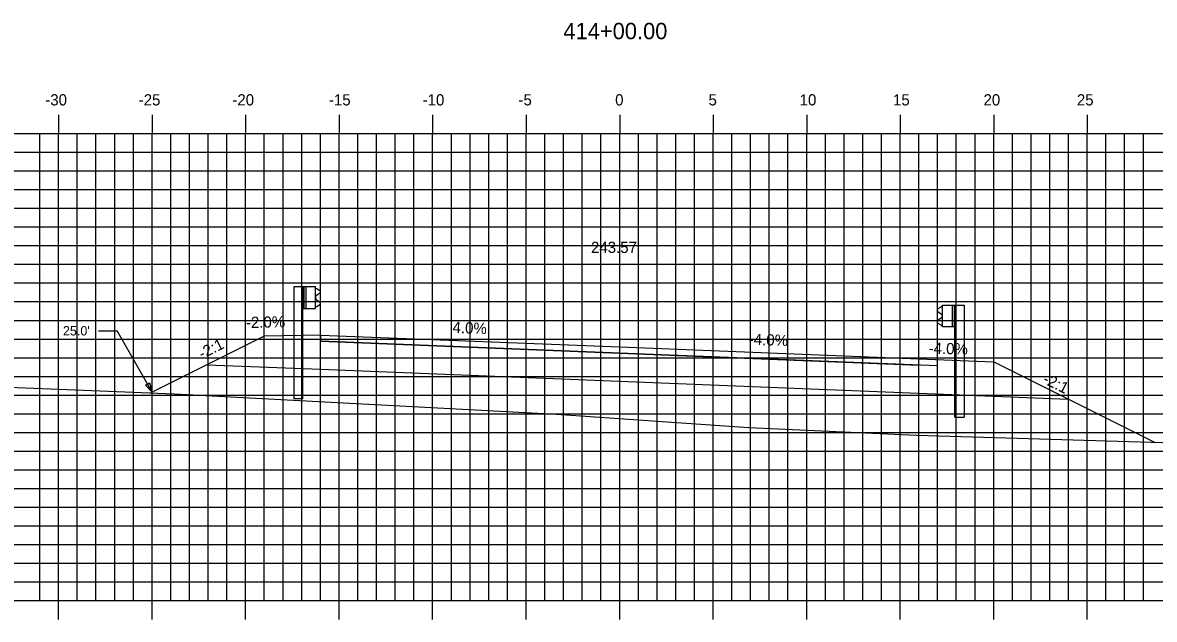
# Model space of a CAD drawing. Extents: x 1160718 to 1173142, y 616002 to 617630.
# Drawn here: x 1168156.4 to 1168216.9, y 616656.9 to 616688.9 of the extents above; entities that cross this region are included whole.
import ezdxf

# ---------------------------------------------------------------- set-up
doc = ezdxf.new("R2010")
doc.units = 0
for name, color, linetype in [('ANNOTATION', 7, 'Continuous'), ('D_Guardrail_Beam_Lt', 7, 'Continuous'), ('D_Guardrail_Beam_Rt', 7, 'Continuous'), ('D_Roadway_Centerline', 7, 'Continuous'), ('D_Roadway_Centerline_Text', 7, 'Continuous'), ('D_Roadway_Edge_Shoulder', 7, 'Continuous'), ('D_Roadway_Edge_TW', 7, 'Continuous'), ('D_Roadway_Pavement', 7, 'Continuous'), ('D_Roadway_SlopeLines', 7, 'Continuous'), ('D_Roadway_SubGrade', 7, 'Continuous'), ('H_V ANNOTATION', 7, 'Continuous'), ('MAJOR', 7, 'Continuous'), ('MINOR', 7, 'Continuous'), ('S_Roadway_Centerline', 7, 'Continuous'), ('SHADING', 7, 'Continuous')]:
    doc.layers.add(name, color=color, linetype=linetype)

msp = doc.modelspace()

# ---------------------------------------------------------------- linework, layer by layer
at = {"layer": 'ANNOTATION'}
for p, q in [((1168160.476, 616672.369), (1168161.476, 616672.369)), ((1168163.342, 616669.083), (1168161.476, 616672.369)), ((1168204.342, 616670.863), (1168208.338, 616670.703))]:
    msp.add_line(p, q, dxfattribs=at)
msp.add_lwpolyline([(1168163.203, 616669.579), (1168163.342, 616669.083), (1168162.986, 616669.456)], close=True, dxfattribs=at)
at = {"layer": 'D_Guardrail_Beam_Lt'}
for p, q in [((1168170.916, 616674.726), (1168170.916, 616668.726)), ((1168171.387, 616674.726), (1168170.916, 616674.726)), ((1168172.074, 616674.726), (1168171.387, 616674.726)), ((1168171.387, 616674.726), (1168171.387, 616673.559)), ((1168171.449, 616674.726), (1168171.449, 616673.559)), ((1168171.553, 616674.726), (1168171.553, 616673.559)), ((1168172.074, 616673.559), (1168172.074, 616674.726)), ((1168172.074, 616674.643), (1168172.148, 616674.628)), ((1168172.164, 616674.621), (1168172.308, 616674.521)), ((1168172.079, 616674.178), (1168172.079, 616674.108)), ((1168172.308, 616674.378), (1168172.112, 616674.242)), ((1168172.112, 616674.043), (1168172.308, 616673.907)), ((1168171.387, 616673.559), (1168172.074, 616673.559)), ((1168171.408, 616668.726), (1168171.408, 616673.559)), ((1168172.148, 616673.657), (1168172.074, 616673.643)), ((1168172.308, 616673.764), (1168172.164, 616673.664)), ((1168171.408, 616668.726), (1168170.916, 616668.726))]:
    msp.add_line(p, q, dxfattribs=at)
for centre, major_axis, start_param, end_param in [((1168172.14, 616674.587), (0.0417, 0), 0.959931, 1.376053), ((1168172.257, 616674.45), (0.0877, 0), 5.323254, 7.243116), ((1168172.158, 616674.178), (-0.0789, 0), 5.323254, 6.283185), ((1168172.158, 616674.108), (-0.0789, 0), 6.283185, 7.243116), ((1168172.257, 616673.836), (0.0877, 0), 5.323254, 7.243116), ((1168172.14, 616673.698), (0.0417, 0), 4.907132, 5.323254)]:
    msp.add_ellipse(centre, major_axis=major_axis, ratio=0.995501, start_param=start_param, end_param=end_param, dxfattribs=at)
at = {"layer": 'D_Guardrail_Beam_Rt'}
for p, q in [((1168205.505, 616673.638), (1168205.361, 616673.538)), ((1168205.361, 616673.394), (1168205.557, 616673.258)), ((1168205.595, 616673.659), (1168205.521, 616673.644)), ((1168205.595, 616673.742), (1168206.282, 616673.742)), ((1168205.595, 616672.575), (1168205.595, 616673.742)), ((1168206.116, 616673.742), (1168206.116, 616672.575)), ((1168206.22, 616673.742), (1168206.22, 616672.575)), ((1168206.282, 616673.742), (1168206.753, 616673.742)), ((1168206.282, 616673.742), (1168206.282, 616672.575)), ((1168206.753, 616673.742), (1168206.753, 616667.742)), ((1168205.557, 616673.059), (1168205.361, 616672.923)), ((1168205.361, 616672.78), (1168205.505, 616672.68)), ((1168205.521, 616672.673), (1168205.595, 616672.659)), ((1168205.59, 616673.194), (1168205.59, 616673.124)), ((1168206.282, 616672.575), (1168205.595, 616672.575)), ((1168206.261, 616667.742), (1168206.261, 616672.575)), ((1168206.261, 616667.742), (1168206.753, 616667.742))]:
    msp.add_line(p, q, dxfattribs=at)
for centre, major_axis, start_param, end_param in [((1168205.412, 616673.466), (-0.0877, 0), 5.323254, 7.243116), ((1168205.529, 616673.604), (-0.0417, 0), 4.907132, 5.323254), ((1168205.511, 616673.194), (0.0789, 0), 0, 0.959931), ((1168205.412, 616672.852), (-0.0877, 0), 5.323254, 7.243116), ((1168205.529, 616672.714), (-0.0417, 0), 0.959931, 1.376053), ((1168205.511, 616673.124), (0.0789, 0), 5.323254, 6.283185)]:
    msp.add_ellipse(centre, major_axis=major_axis, ratio=0.995501, start_param=start_param, end_param=end_param, dxfattribs=at)
at = {"layer": 'D_Roadway_Edge_Shoulder'}
msp.add_lwpolyline([(1168172.342, 616672.143), (1168172.342, 616671.81)], dxfattribs=at)
at = {"layer": 'D_Roadway_Edge_TW'}
for p, q in [((1168172.342, 616671.81), (1168172.342, 616672.143)), ((1168172.342, 616672.143), (1168188.342, 616671.503)), ((1168188.342, 616671.17), (1168172.342, 616671.81)), ((1168188.342, 616671.503), (1168204.342, 616670.863)), ((1168205.342, 616670.49), (1168188.342, 616671.17))]:
    msp.add_line(p, q, dxfattribs=at)
at = {"layer": 'D_Roadway_Pavement'}
msp.add_lwpolyline([(1168172.342, 616671.81), (1168172.342, 616671.81), (1168188.342, 616671.17), (1168204.342, 616670.53), (1168204.342, 616670.53), (1168188.342, 616671.17)], close=True, dxfattribs=at)
for points in [[(1168172.342, 616671.81), (1168172.342, 616671.81)], [(1168172.342, 616671.81), (1168172.342, 616671.81)], [(1168204.342, 616670.53), (1168204.342, 616670.53)], [(1168204.342, 616670.53), (1168204.342, 616670.53)]]:
    msp.add_lwpolyline(points, dxfattribs=at)
at = {"layer": 'D_Roadway_SlopeLines'}
for points in [[(1168169.342, 616672.083), (1168163.283, 616669.054)], [(1168208.342, 616670.703), (1168216.931, 616666.408)]]:
    msp.add_lwpolyline(points, dxfattribs=at)
at = {"layer": 'D_Roadway_SubGrade'}
for p, q in [((1168172.342, 616672.143), (1168169.342, 616672.083)), ((1168172.342, 616670.31), (1168172.342, 616672.143)), ((1168172.342, 616670.31), (1168172.342, 616671.81)), ((1168172.342, 616671.81), (1168188.342, 616671.17)), ((1168188.342, 616671.17), (1168204.342, 616670.53)), ((1168205.342, 616668.99), (1168205.342, 616670.823))]:
    msp.add_line(p, q, dxfattribs=at)
at = {"layer": 'MAJOR'}
for p, q in [((1168158.342, 616683.93), (1168158.342, 616682.928)), ((1168163.342, 616683.93), (1168163.342, 616682.928)), ((1168168.342, 616683.93), (1168168.342, 616682.928)), ((1168173.342, 616683.93), (1168173.342, 616682.928)), ((1168178.342, 616683.93), (1168178.342, 616682.928)), ((1168183.342, 616683.93), (1168183.342, 616682.928)), ((1168188.342, 616683.93), (1168188.342, 616682.928)), ((1168193.342, 616683.93), (1168193.342, 616682.928)), ((1168198.342, 616683.93), (1168198.342, 616682.928)), ((1168203.342, 616683.93), (1168203.342, 616682.928)), ((1168208.342, 616683.93), (1168208.342, 616682.928)), ((1168213.342, 616683.93), (1168213.342, 616682.928)), ((1168118.342, 616682.928), (1168258.342, 616682.928)), ((1168118.342, 616682.928), (1168258.342, 616682.928)), ((1168158.342, 616657.928), (1168158.342, 616682.928)), ((1168163.342, 616657.928), (1168163.342, 616682.928)), ((1168168.342, 616657.928), (1168168.342, 616682.928)), ((1168173.342, 616657.928), (1168173.342, 616682.928)), ((1168178.342, 616657.928), (1168178.342, 616682.928)), ((1168183.342, 616657.928), (1168183.342, 616682.928)), ((1168188.342, 616657.928), (1168188.342, 616682.928)), ((1168193.342, 616657.928), (1168193.342, 616682.928)), ((1168198.342, 616657.928), (1168198.342, 616682.928)), ((1168203.342, 616657.928), (1168203.342, 616682.928)), ((1168208.342, 616657.928), (1168208.342, 616682.928)), ((1168213.342, 616657.928), (1168213.342, 616682.928)), ((1168118.342, 616677.928), (1168258.342, 616677.928)), ((1168118.342, 616672.928), (1168258.342, 616672.928)), ((1168118.342, 616667.928), (1168258.342, 616667.928)), ((1168118.342, 616662.928), (1168258.342, 616662.928)), ((1168118.342, 616657.928), (1168258.342, 616657.928)), ((1168118.342, 616657.928), (1168258.342, 616657.928)), ((1168158.342, 616656.926), (1168158.342, 616657.928)), ((1168163.342, 616656.926), (1168163.342, 616657.928)), ((1168168.342, 616656.926), (1168168.342, 616657.928)), ((1168173.342, 616656.926), (1168173.342, 616657.928)), ((1168178.342, 616656.926), (1168178.342, 616657.928)), ((1168183.342, 616656.926), (1168183.342, 616657.928)), ((1168188.342, 616656.926), (1168188.342, 616657.928)), ((1168193.342, 616656.926), (1168193.342, 616657.928)), ((1168198.342, 616656.926), (1168198.342, 616657.928)), ((1168203.342, 616656.926), (1168203.342, 616657.928)), ((1168208.342, 616656.926), (1168208.342, 616657.928)), ((1168213.342, 616656.926), (1168213.342, 616657.928))]:
    msp.add_line(p, q, dxfattribs=at)
at = {"layer": 'MINOR'}
for p, q in [((1168157.342, 616657.928), (1168157.342, 616682.928)), ((1168159.342, 616657.928), (1168159.342, 616682.928)), ((1168160.342, 616657.928), (1168160.342, 616682.928)), ((1168161.342, 616657.928), (1168161.342, 616682.928)), ((1168162.342, 616657.928), (1168162.342, 616682.928)), ((1168164.342, 616657.928), (1168164.342, 616682.928)), ((1168165.342, 616657.928), (1168165.342, 616682.928)), ((1168166.342, 616657.928), (1168166.342, 616682.928)), ((1168167.342, 616657.928), (1168167.342, 616682.928)), ((1168169.342, 616657.928), (1168169.342, 616682.928)), ((1168170.342, 616657.928), (1168170.342, 616682.928)), ((1168171.342, 616657.928), (1168171.342, 616682.928)), ((1168172.342, 616657.928), (1168172.342, 616682.928)), ((1168174.342, 616657.928), (1168174.342, 616682.928)), ((1168175.342, 616657.928), (1168175.342, 616682.928)), ((1168176.342, 616657.928), (1168176.342, 616682.928)), ((1168177.342, 616657.928), (1168177.342, 616682.928)), ((1168179.342, 616657.928), (1168179.342, 616682.928)), ((1168180.342, 616657.928), (1168180.342, 616682.928)), ((1168181.342, 616657.928), (1168181.342, 616682.928)), ((1168182.342, 616657.928), (1168182.342, 616682.928)), ((1168184.342, 616657.928), (1168184.342, 616682.928)), ((1168185.342, 616657.928), (1168185.342, 616682.928)), ((1168186.342, 616657.928), (1168186.342, 616682.928)), ((1168187.342, 616657.928), (1168187.342, 616682.928)), ((1168189.342, 616657.928), (1168189.342, 616682.928)), ((1168190.342, 616657.928), (1168190.342, 616682.928)), ((1168191.342, 616657.928), (1168191.342, 616682.928)), ((1168192.342, 616657.928), (1168192.342, 616682.928)), ((1168194.342, 616657.928), (1168194.342, 616682.928)), ((1168195.342, 616657.928), (1168195.342, 616682.928)), ((1168196.342, 616657.928), (1168196.342, 616682.928)), ((1168197.342, 616657.928), (1168197.342, 616682.928)), ((1168199.342, 616657.928), (1168199.342, 616682.928)), ((1168200.342, 616657.928), (1168200.342, 616682.928)), ((1168201.342, 616657.928), (1168201.342, 616682.928)), ((1168202.342, 616657.928), (1168202.342, 616682.928)), ((1168204.342, 616657.928), (1168204.342, 616682.928)), ((1168205.342, 616657.928), (1168205.342, 616682.928)), ((1168206.342, 616657.928), (1168206.342, 616682.928)), ((1168207.342, 616657.928), (1168207.342, 616682.928)), ((1168209.342, 616657.928), (1168209.342, 616682.928)), ((1168210.342, 616657.928), (1168210.342, 616682.928)), ((1168211.342, 616657.928), (1168211.342, 616682.928)), ((1168212.342, 616657.928), (1168212.342, 616682.928)), ((1168214.342, 616657.928), (1168214.342, 616682.928)), ((1168215.342, 616657.928), (1168215.342, 616682.928)), ((1168216.342, 616657.928), (1168216.342, 616682.928)), ((1168118.342, 616681.928), (1168258.342, 616681.928)), ((1168118.342, 616680.928), (1168258.342, 616680.928)), ((1168118.342, 616679.928), (1168258.342, 616679.928)), ((1168118.342, 616678.928), (1168258.342, 616678.928)), ((1168118.342, 616676.928), (1168258.342, 616676.928)), ((1168118.342, 616675.928), (1168258.342, 616675.928)), ((1168118.342, 616674.928), (1168258.342, 616674.928)), ((1168118.342, 616673.928), (1168258.342, 616673.928)), ((1168118.342, 616671.928), (1168258.342, 616671.928)), ((1168118.342, 616670.928), (1168258.342, 616670.928)), ((1168118.342, 616669.928), (1168258.342, 616669.928)), ((1168118.342, 616668.928), (1168258.342, 616668.928)), ((1168118.342, 616666.928), (1168258.342, 616666.928)), ((1168118.342, 616665.928), (1168258.342, 616665.928)), ((1168118.342, 616664.928), (1168258.342, 616664.928)), ((1168118.342, 616663.928), (1168258.342, 616663.928)), ((1168118.342, 616661.928), (1168258.342, 616661.928)), ((1168118.342, 616660.928), (1168258.342, 616660.928)), ((1168118.342, 616659.928), (1168258.342, 616659.928)), ((1168118.342, 616658.928), (1168258.342, 616658.928))]:
    msp.add_line(p, q, dxfattribs=at)
at = {"layer": 'S_Roadway_Centerline'}
msp.add_lwpolyline([(1168118.342, 616670.986), (1168130.612, 616670.558), (1168140.361, 616670.013), (1168144.163, 616669.811), (1168164.541, 616669.004), (1168184.956, 616667.903), (1168195.253, 616667.189), (1168204.218, 616666.784), (1168217.369, 616666.395), (1168223.021, 616665.786), (1168228.097, 616665.226), (1168239.076, 616668.338), (1168250.436, 616671.804), (1168253.197, 616672.394), (1168253.618, 616672.45), (1168253.622, 616672.451), (1168253.68, 616672.454), (1168258.057, 616672.707), (1168258.342, 616672.709)], dxfattribs=at)
at = {"layer": 'SHADING'}
msp.add_lwpolyline([(1168166.28, 616670.552), (1168172.342, 616670.31), (1168212.327, 616668.71)], dxfattribs=at)

# ---------------------------------------------------------------- texts
at = {"layer": 'ANNOTATION'}
for s, rotation, p in [('-2.0%', 1.14576, (1168168.364, 616672.514)), ('4.0%', 357.70939, (1168179.398, 616672.261)), ('-4.0%', 357.70939, (1168195.237, 616671.628)), ('-2:1', 26.56505, (1168166.006, 616670.839)), ('-4.0%', 358.85424, (1168204.857, 616671.139)), ('-2:1', 333.43495, (1168210.919, 616669.599))]:
    msp.add_text(s, height=0.6, rotation=rotation, dxfattribs=at).set_placement(p)
msp.add_text("25.0'", height=0.5, dxfattribs=at).set_placement((1168158.576, 616672.119))
at = {"layer": 'D_Roadway_Centerline'}
for s, p in [('C', (1168188.336, 616671.503)), ('L', (1168188.342, 616671.496))]:
    msp.add_text(s, height=0.0146, dxfattribs=at).set_placement(p)
at = {"layer": 'D_Roadway_Centerline_Text'}
msp.add_text('243.57', height=0.6, dxfattribs=at).set_placement((1168186.811, 616676.535))
at = {"layer": 'H_V ANNOTATION'}
for s, height, p in [('414+00.00', 0.875, (1168185.33, 616687.971)), ('-30', 0.6, (1168157.63, 616684.428)), ('-25', 0.6, (1168162.627, 616684.428)), ('-20', 0.6, (1168167.635, 616684.428)), ('-15', 0.6, (1168172.798, 616684.428)), ('-10', 0.6, (1168177.806, 616684.428)), ('-5', 0.6, (1168182.932, 616684.428)), ('0', 0.6, (1168188.101, 616684.428)), ('5', 0.6, (1168193.093, 616684.428)), ('10', 0.6, (1168197.967, 616684.428)), ('15', 0.6, (1168202.959, 616684.428)), ('20', 0.6, (1168207.796, 616684.428)), ('25', 0.6, (1168212.788, 616684.428))]:
    msp.add_text(s, height=height, dxfattribs=at).set_placement(p)

doc.saveas('drawing.dxf')
